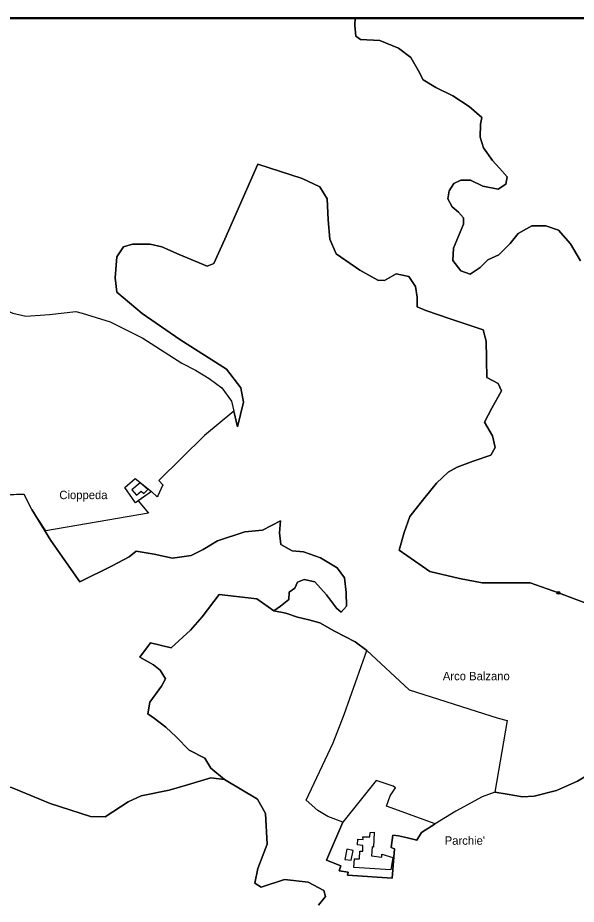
# Model space of a CAD drawing. Extents: x 650071 to 653841, y 889105 to 891996.
# Drawn here: x 652704 to 653235, y 891152 to 891996 of the extents above; entities that cross this region are included whole.
import ezdxf
from ezdxf.enums import TextEntityAlignment as Align

# ---------------------------------------------------------------- set-up
doc = ezdxf.new("R2010")
doc.units = 0
doc.header["$LTSCALE"] = 5.6
doc.header["$PDMODE"] = 32
doc.header["$PDSIZE"] = 2.8
for name, color, linetype, lineweight in [('2', 7, 'Continuous', 25), ('25', 7, 'Continuous', 25), ('34', 7, 'Continuous', 25), ('36', 7, 'Continuous', 25), ('37', 7, 'Continuous', 25), ('61', 7, 'Continuous', 35)]:
    doc.layers.add(name, color=color, linetype=linetype, lineweight=lineweight)
doc.layers.add('60', color=7, linetype='Continuous')

msp = doc.modelspace()

# ---------------------------------------------------------------- linework, layer by layer
at = {"layer": '2'}
for points in [[(652806.19, 891549.08), (652815.93, 891557.51), (652831.45, 891545.12), (652816.05, 891534.52), (652813.22, 891538.64)], [(652820.52, 891553.54), (652812.75, 891546.75), (652817.26, 891541.63), (652821.56, 891545.62), (652824.05, 891543.28), (652827.8, 891547.15)], [(653039.26, 891220.94), (653043.01, 891220.96), (653042.56, 891206.86), (653041.2, 891207), (653040.68, 891198.64), (653050.24, 891197.46), (653050.52, 891200.03), (653060.83, 891197.09), (653058.85, 891185.29), (653023.8, 891187.53), (653024.24, 891195.71), (653029.05, 891195.61), (653029.39, 891202.87), (653032.24, 891202.87), (653032.32, 891208.42), (653027.34, 891209.13), (653027.62, 891214.53), (653032.53, 891214.28), (653032.42, 891216.74), (653038.91, 891216.64)], [(653016.96, 891204.86), (653015.25, 891195.05), (653021.22, 891194.48), (653023.07, 891203.58)]]:
    msp.add_lwpolyline(points, close=True, dxfattribs=at)
for points in [[(653054.75, 891245.92), (653058.29, 891255.81), (653063.45, 891263.32), (653061.28, 891264.95), (653044.85, 891270.22), (653013.35, 891230.72)], [(653013.35, 891230.72), (652997.9, 891194.34), (653011.28, 891188.99), (653009.68, 891184.43), (653018.51, 891183.09), (653017.71, 891180.15), (653060.27, 891177.47), (653062.52, 891205.17), (653059.32, 891206.54), (653060.75, 891218.12), (653066.15, 891217.62), (653074.85, 891215.82), (653083.55, 891213.52), (653088.15, 891220.72), (653100.95, 891229.02), (653054.75, 891245.92)]]:
    msp.add_lwpolyline(points, dxfattribs=at)
at = {"layer": '25'}
for points in [[(652620.48, 891711.24), (652634.54, 891714.91), (652666.43, 891716.48), (652688.6, 891719.63), (652699.41, 891714.91), (652711.85, 891712.03), (652734.56, 891713.6), (652759.44, 891716.55), (652765.39, 891715.04), (652792.1, 891706.88)], [(652792.1, 891706.88), (652823.26, 891691.28), (652860.27, 891667.46), (652873.24, 891660.65), (652886.32, 891652.68), (652898.19, 891643.77), (652907.3, 891631.28), (652909.52, 891621.75), (652881.72, 891598.46), (652838.34, 891555.71)], [(652838.34, 891555.71), (652842.22, 891551.71), (652837.47, 891541.02), (652836.84, 891540.09), (652831.45, 891545.12), (652818.8, 891536.42), (652828.59, 891524.59), (652731.09, 891507.71), (652717.78, 891528.11), (652710.21, 891542.27), (652691.29, 891541.75), (652666.75, 891552.35), (652657.22, 891552.76), (652590.41, 891560.52), (652577.75, 891561.68), (652570.72, 891565.87), (652570.72, 891569.46)]]:
    msp.add_lwpolyline(points, dxfattribs=at)
at = {"layer": '34'}
msp.add_lwpolyline([(653004.13, 891306.12), (653014.51, 891332.96), (653036.28, 891393.87), (653076.27, 891356.53), (653161.08, 891329.54), (653169.56, 891327.27), (653157.88, 891259.31), (653145.74, 891254.87), (653120.71, 891241.08), (653100.95, 891229.02), (653054.75, 891245.92), (653058.29, 891255.81), (653063.45, 891263.32), (653061.28, 891264.95), (653044.85, 891270.22), (653013.35, 891230.72), (652998.89, 891236.03), (652989.54, 891241.64), (652978.47, 891251.46)], close=True, dxfattribs=at)
at = {"layer": '36'}
for points in [[(653161.11, 891833.09), (653168.28, 891837.65), (653169.5, 891844.57), (653162.17, 891852.92), (653155.7, 891860.36), (653147.06, 891872.42), (653143.81, 891882.39), (653144.35, 891894.97), (653145.43, 891901.27), (653133.54, 891911.76), (653117.86, 891921.72), (653101.64, 891929.59), (653089.75, 891936.93), (653085.12, 891945.63), (653078.09, 891958.21), (653066.2, 891967.13), (653048.36, 891974.47), (653029.98, 891975.52), (653025.65, 891978.67), (653024.57, 891988.63), (653024.92, 891996.11), (652608.22, 891996.11)], [(652901.08, 891785.45), (652932.43, 891856.78), (652974.61, 891843.14), (652991.37, 891835.28), (652998.39, 891823.74), (652999.48, 891803.81), (653001.1, 891785.45), (653007.04, 891771.29), (653029.51, 891755.88), (653046.57, 891746.48), (653052.82, 891746.05), (653064.11, 891752.51), (653076.01, 891749.89), (653082.5, 891740.45), (653084.05, 891730.34), (653084.12, 891721.04), (653092.23, 891717.37), (653115.48, 891709.5), (653146.83, 891699.01), (653149.57, 891688.4), (653149.93, 891672.24), (653149.98, 891670.28), (653150.08, 891653.91), (653161.03, 891648.2), (653164.13, 891641.12), (653154.94, 891624.54), (653147.94, 891611.23), (653155.48, 891598.32), (653158.19, 891587.3), (653153.86, 891579.96), (653137.1, 891574.19), (653121.96, 891568.42), (653113.35, 891563.59), (653102.22, 891553.19), (653090.35, 891538.34), (653077.09, 891521.54), (653071.68, 891506.33), (653066.83, 891489.51), (653096.08, 891469.11), (653124.23, 891462.48)], [(653239.42, 891764.63), (653229.69, 891780.88), (653218.34, 891793.99), (653206.44, 891798.19), (653192.93, 891798.19), (653179.95, 891790.85), (653172.38, 891781.41), (653161.57, 891770.4), (653151.3, 891765.68), (653143.73, 891758.33), (653134.52, 891752.13), (653125.56, 891755.19), (653117.78, 891765.15), (653118.44, 891776.97), (653127.99, 891799.57), (653128.13, 891805.82), (653123.31, 891811.18), (653117.2, 891816.07), (653113.14, 891823.8), (653114.36, 891831.34), (653118.94, 891838.34), (653125.43, 891841.48), (653134.62, 891841.48), (653146.51, 891835.71), (653161.11, 891833.09)], [(652699.41, 891714.91), (652711.85, 891712.03), (652734.56, 891713.6), (652759.44, 891716.55), (652765.39, 891715.04), (652792.1, 891706.88), (652823.26, 891691.28), (652860.27, 891667.46), (652873.24, 891660.65), (652886.32, 891652.68), (652898.19, 891643.77), (652907.3, 891631.28), (652913.22, 891606.66), (652918.92, 891630.21), (652916.22, 891643.85), (652902.7, 891661.68), (652858.37, 891690), (652822.68, 891714.65), (652798.35, 891735.1), (652796.73, 891748.74), (652798.35, 891768.67), (652804.84, 891778.11), (652813.49, 891780.73), (652830.25, 891780.73), (652841.07, 891778.11), (652857.83, 891770.77), (652884.32, 891759.75), (652890.8, 891762.38), (652901.08, 891785.45)], [(652880.6, 891490.16), (652869.05, 891484.27), (652851.21, 891481.99), (652833.91, 891485.66), (652816.71, 891488.5), (652810.23, 891483.01), (652794.01, 891474.62), (652763.19, 891459.41), (652735.62, 891498.74), (652717.78, 891528.11), (652710.21, 891542.27), (652703.18, 891542.27), (652691.29, 891541.75), (652684.8, 891543.84), (652665.88, 891552.76), (652657.22, 891552.76), (652623.16, 891556.43), (652595.05, 891560.1), (652590.41, 891560.53)], [(652965.03, 891488.77), (652954.43, 891494.69), (652953.19, 891506.04), (652953.93, 891517.39), (652936.97, 891508.36), (652920.21, 891506.78), (652894.2, 891498.38), (652880.6, 891490.16)], [(652865.68, 891266.19), (652887.77, 891272.9), (652900.87, 891271.37), (652887.77, 891281.92), (652882.18, 891291.4), (652867.14, 891299.29), (652854.79, 891311.81), (652844.94, 891321), (652834.24, 891329.12), (652827.79, 891333.68), (652829.95, 891344.69), (652840.77, 891359.9), (652844.7, 891366.89), (652839.68, 891375.11), (652833.2, 891380.36), (652820.22, 891387.7), (652830.4, 891401.19), (652849.96, 891396.61), (652868.62, 891413.28), (652879.69, 891425.98), (652895.74, 891447.32), (652931.59, 891443.29), (652947.77, 891431.77), (652953.93, 891436.21), (652961.82, 891442.63), (652962.41, 891449.58), (652967.82, 891453.25), (652970.21, 891458.91), (652976.47, 891461.65), (652986.73, 891459.4), (652997.82, 891446.82), (653007.28, 891434.37), (653011.88, 891430.54), (653016.81, 891436.21), (653016.47, 891449.06), (653014.85, 891463.22), (653007.82, 891472.66), (652992.15, 891482.1), (652975.88, 891487.78), (652965.03, 891488.77)], [(653124.23, 891462.48), (653145.86, 891458.28), (653171.81, 891458.28), (653191.27, 891458.28), (653218.3, 891448.84)], [(653218.3, 891448.84), (653251.82, 891436.25)], [(652900.87, 891271.37), (652887.77, 891272.9), (652865.68, 891266.19)], [(652990.19, 891151.53), (652996.77, 891159.92), (652995.18, 891165.5), (652980.42, 891173.49), (652957.69, 891176.08), (652935.55, 891168.7), (652929.77, 891172.49), (652932.56, 891186.66), (652941.33, 891209.6), (652939.75, 891238.89), (652932.19, 891252.51), (652900.87, 891271.37)], [(652773.4, 891235.97), (652735.03, 891248.47), (652698.18, 891263.67), (652690.68, 891264.04), (652683.92, 891262.27)], [(652690.68, 891264.04), (652698.18, 891263.67), (652735.03, 891248.47)], [(652865.68, 891266.19), (652848.34, 891261.15), (652821.5, 891255.55), (652809.19, 891249.96)], [(652821.5, 891255.55), (652848.34, 891261.15), (652865.68, 891266.19)], [(652735.03, 891248.47), (652773.4, 891235.97), (652787.38, 891235.69), (652809.19, 891249.96), (652821.5, 891255.55)], [(652809.19, 891249.96), (652787.38, 891235.69), (652773.4, 891235.97)]]:
    msp.add_lwpolyline(points, dxfattribs=at)
msp.add_point((653218.3, 891448.84), dxfattribs=at)
at = {"layer": '37'}
for points in [[(653294.8, 891995.96), (653024.92, 891996.11), (653024.57, 891988.63), (653025.65, 891978.67), (653029.98, 891975.52), (653048.36, 891974.47), (653066.2, 891967.13), (653078.09, 891958.21), (653085.12, 891945.63), (653089.75, 891936.93), (653101.64, 891929.59), (653117.86, 891921.72), (653133.54, 891911.76), (653145.43, 891901.27), (653144.35, 891894.97), (653143.81, 891882.39), (653147.06, 891872.42), (653155.7, 891860.36), (653162.17, 891852.92), (653169.5, 891844.57), (653168.28, 891837.65), (653161.11, 891833.09), (653146.51, 891835.71), (653134.62, 891841.48), (653125.43, 891841.48), (653118.94, 891838.34), (653114.36, 891831.34), (653113.14, 891823.8), (653117.2, 891816.07), (653123.31, 891811.18), (653128.13, 891805.82), (653127.99, 891799.57), (653118.44, 891776.97), (653117.78, 891765.15), (653125.56, 891755.19), (653134.52, 891752.13), (653143.73, 891758.33), (653151.3, 891765.68), (653161.57, 891770.4)], [(652998.39, 891823.74), (652991.37, 891835.28), (652974.61, 891843.14), (652932.43, 891856.78), (652901.08, 891785.45), (652890.8, 891762.38), (652884.32, 891759.75), (652857.83, 891770.77), (652841.07, 891778.11), (652830.25, 891780.73), (652813.49, 891780.73), (652804.84, 891778.11), (652798.35, 891768.67), (652796.73, 891748.74), (652798.35, 891735.1), (652822.68, 891714.65), (652858.37, 891690), (652902.7, 891661.68), (652916.22, 891643.85), (652918.92, 891630.21), (652913.22, 891606.66), (652909.59, 891621.77)], [(653218.3, 891448.84), (653191.27, 891458.28), (653171.81, 891458.28), (653145.86, 891458.28), (653124.23, 891462.48), (653096.08, 891469.11), (653066.83, 891489.51), (653071.68, 891506.33), (653077.09, 891521.54), (653090.35, 891538.34), (653102.22, 891553.19), (653113.35, 891563.59), (653121.96, 891568.42), (653137.1, 891574.19), (653153.86, 891579.96), (653158.19, 891587.3), (653155.48, 891598.32), (653147.94, 891611.23), (653154.94, 891624.54), (653164.13, 891641.12), (653161.03, 891648.2), (653150.08, 891653.91), (653149.98, 891670.28), (653149.93, 891672.24), (653149.57, 891688.4), (653146.83, 891699.01), (653115.48, 891709.5), (653092.23, 891717.37), (653084.12, 891721.04), (653084.05, 891730.34), (653082.5, 891740.45), (653076.01, 891749.89), (653064.11, 891752.51), (653052.82, 891746.05), (653046.57, 891746.48), (653029.51, 891755.88), (653007.04, 891771.29), (653001.1, 891785.45), (652999.48, 891803.81), (652998.39, 891823.74)], [(653161.57, 891770.4), (653172.38, 891781.41), (653179.95, 891790.85), (653192.93, 891798.19), (653206.44, 891798.19), (653218.34, 891793.99), (653229.69, 891780.88), (653239.42, 891764.63)], [(652909.52, 891621.75), (652881.72, 891598.46), (652838.34, 891555.71)], [(652838.34, 891555.71), (652842.22, 891551.71), (652837.47, 891541.02), (652836.84, 891540.09), (652831.45, 891545.12), (652818.8, 891536.42)], [(652818.8, 891536.42), (652828.59, 891524.59), (652731.09, 891507.71), (652717.78, 891528.11), (652735.62, 891498.74), (652763.19, 891459.41), (652794.01, 891474.62), (652810.23, 891483.01), (652816.71, 891488.5), (652833.91, 891485.66), (652851.21, 891481.99)], [(652851.21, 891481.99), (652869.05, 891484.27), (652880.6, 891490.16), (652894.2, 891498.38), (652920.21, 891506.78), (652936.97, 891508.36), (652953.93, 891517.39), (652953.19, 891506.04), (652954.43, 891494.69), (652965.03, 891488.77)], [(652965.03, 891488.77), (652975.88, 891487.78), (652992.15, 891482.1), (653007.82, 891472.66), (653014.85, 891463.22), (653016.47, 891449.06), (653016.81, 891436.21), (653011.88, 891430.54), (653007.28, 891434.37), (652997.82, 891446.82), (652986.73, 891459.4), (652976.47, 891461.65), (652970.21, 891458.91), (652967.82, 891453.25), (652962.41, 891449.58), (652961.82, 891442.63), (652953.93, 891436.21), (652947.77, 891431.77)], [(653036.28, 891393.87), (653025.12, 891402.32), (653005.39, 891412.29), (652991.43, 891420.28), (652981.01, 891423.16), (652970.16, 891425.6), (652959.07, 891429.37), (652947.77, 891431.77), (652931.59, 891443.29), (652895.74, 891447.32), (652879.69, 891425.98), (652868.62, 891413.28), (652849.96, 891396.61), (652830.4, 891401.19), (652820.22, 891387.7), (652833.2, 891380.36), (652839.68, 891375.11), (652844.7, 891366.89), (652840.77, 891359.9), (652829.95, 891344.69), (652827.79, 891333.68), (652834.24, 891329.12), (652844.94, 891321), (652854.79, 891311.81), (652867.14, 891299.29), (652882.18, 891291.4), (652887.77, 891281.92), (652900.87, 891271.37), (652932.19, 891252.51), (652939.75, 891238.89), (652941.33, 891209.6), (652932.56, 891186.66), (652929.77, 891172.49), (652935.55, 891168.7), (652957.69, 891176.08), (652980.42, 891173.49), (652995.18, 891165.5), (652996.77, 891159.92), (652990.19, 891151.53)], [(653251.82, 891436.25), (653218.3, 891448.84)], [(652947.77, 891431.77), (652959.07, 891429.37), (652970.16, 891425.6), (652981.01, 891423.16)], [(652981.01, 891423.16), (652991.43, 891420.28), (653005.39, 891412.29), (653025.12, 891402.32), (653036.28, 891393.87)], [(653004.13, 891306.12), (653014.51, 891332.96), (653036.28, 891393.87)], [(653036.28, 891393.87), (653076.27, 891356.53), (653161.08, 891329.54), (653169.56, 891327.27), (653157.88, 891259.31)], [(653013.35, 891230.72), (652998.89, 891236.03), (652989.54, 891241.64), (652978.47, 891251.46), (653004.13, 891306.12)], [(653157.88, 891259.31), (653169.6, 891257.3), (653184.23, 891254.64), (653195.31, 891255.3), (653216.37, 891260.63), (653236.31, 891269.72), (653250.82, 891278.15), (653259.68, 891285.69), (653278.74, 891306.98)], [(653278.74, 891306.98), (653259.68, 891285.69), (653250.82, 891278.15), (653236.31, 891269.72), (653216.37, 891260.63), (653195.31, 891255.3), (653184.23, 891254.64), (653169.6, 891257.3), (653157.88, 891259.31)], [(653157.88, 891259.31), (653145.74, 891254.87), (653120.71, 891241.08), (653100.95, 891229.02), (653088.15, 891220.72), (653083.55, 891213.52), (653074.85, 891215.82), (653066.15, 891217.62), (653060.75, 891218.12), (653059.32, 891206.54), (653062.52, 891205.17), (653060.27, 891177.47), (653017.71, 891180.15), (653018.51, 891183.09), (653009.68, 891184.43), (653011.28, 891188.99), (652997.9, 891194.34), (653013.35, 891230.72)]]:
    msp.add_lwpolyline(points, dxfattribs=at)
msp.add_point((653218.3, 891448.84), dxfattribs=at)
at = {"layer": '61', "lineweight": 40}
msp.add_lwpolyline([(653839.81, 891995.66), (653839.8, 889106.04), (652174.44, 889106.04), (652174.45, 891995.66)], close=True, dxfattribs=at)

# ---------------------------------------------------------------- texts
at = {"layer": '60'}
for s, p in [('Cioppeda', (652766.67, 891538.02)), ('Arco Balzano', (653140.2, 891365.66)), ("Parchie'", (653129.31, 891209.12))]:
    msp.add_text(s, height=8, dxfattribs=at).set_placement(p, align=Align.CENTER)

doc.saveas('drawing.dxf')
